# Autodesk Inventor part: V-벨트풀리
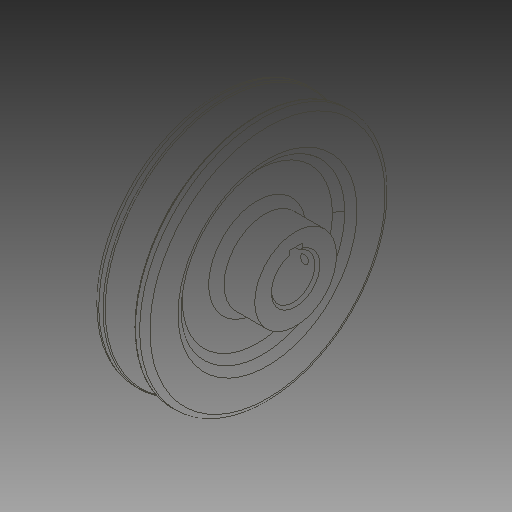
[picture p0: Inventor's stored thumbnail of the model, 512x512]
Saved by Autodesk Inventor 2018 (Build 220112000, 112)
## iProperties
Created: 2015-09
Part Number: V-벨트풀리
Material: 강철, 연강
Document SubType Name: Modeling
Designer: mduedu
Density: 7.86 g/cm^3
Mass: 779.014 g
Surface Area: 277.465 cm^2
Volume: 99.1112 cm^3
Appearance: 강철
Author: mduedu
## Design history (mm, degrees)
sketch "스케치1"
  geometry: L1 (-10, 0)-(10, 0); L2 (-10, 0)-(-10, 48); L3 (-10, 48)-(-5.976, 48); L4 (-5.976, 48)-(-2.154, 35.5); L5 (-2.154, 35.5)-(2.154, 35.5); L6 (2.154, 35.5)-(5.976, 48); L7 (5.976, 48)-(10, 48); L8 (10, 48)-(10, 0); L9 (0, 0)-(0, 35.5); L10 (-10, 43.5)-(10, 43.5); 3 further points
  constraints: 20 end point, 6 point on line, 3 perpendicular, 2 midpoint, 2 parallel, 2 symmetric about line, 1 coincident, 1 collinear, 1 equal length, 1 horizontal, 1 vertical, 1 vertical alignment
  dimensions: "d0" = 20 distance between parallel lines of L8 L2; "d2" = 96 diameter of L3 L1; "d3" = 87 diameter of L10 L1; "d4" = 4.5 distance between parallel lines of L10 L3 (derived); "d5" = 8 distance between parallel lines of L5 L10; "d6" = 9.2 distance of point (4.6, 43.5) point (-4.6, 43.5); "d7" = 34 deg angle of L6 L4
revolve "회전1" sketch "스케치1" stored, may be unused: angle "d8" = 90 deg
sketch "스케치2"
  geometry: C1 r 16 at (0, 0); 1 further point
  constraints: 1 centre point, 1 coincident
  dimensions: "d9" = 32 diameter of C1
extrude "돌출1" join sketch "스케치2" distance "d10" = 11; taper "d11" = 0 deg
fillet "모깎기1" dims "d12" = 1, "d13" = 0.5, "d14" = 2
sketch "스케치3"
  geometry: C1 r 16 at (0, 0) reference; C2 r 32 at (0, 0); 1 further point
  constraints: 1 centre point, 1 coincident
  dimensions: "d15" = 64 diameter of C2
extrude "돌출2" cut sketch "스케치3" distance "d16" = 4; taper "d17" = 0 deg
fillet "모깎기2" dims "d18" = 3
fillet "모깎기3" dims "d19" = 3
fillet "모깎기4" dims "d20" = 3
sketch "스케치4"
  geometry: C1 r 8.5 at (0, 0); 1 further point
  constraints: 1 centre point, 1 coincident
  dimensions: "d21" = 17 diameter of C1
extrude "돌출3" cut sketch "스케치4" extent not by distance; stored distance "d22" = 4; taper "d23" = 0 deg
sketch "스케치5"
  geometry: L1 (-2.5, 8.124)-(2.5, 8.124); L2 (2.5, 8.124)-(2.5, 10.8); L3 (2.5, 10.8)-(-2.5, 10.8); L4 (-2.5, 10.8)-(-2.5, 8.124); A1 r 8.5 centre (0, 0) between (-2.5, 8.124) and (2.5, 8.124) reference; 2 further points
  constraints: 8 end point, 3 point on circle, 2 parallel, 1 horizontal, 1 perpendicular, 1 vertical alignment
  dimensions: "d24" = 5 distance of L2.end L3.end; "d26" = 19.3 distance from line of L3 point (0, -8.5)
extrude "돌출4" cut sketch "스케치5" extent not by distance; stored distance "d27" = 4; taper "d28" = 0 deg
chamfer "모따기1" distance "d29" = 1; stored, may be unused: second distance "d30" = 2, angle "d31" = 45 deg
node "작업 평면1"
sketch "스케치6"
  geometry: L1 (-11, 16)-(-11, -16) reference; 2 further points
  constraints: 1 horizontal alignment
  dimensions: "d32" = 5 distance from line of point (-6, 0) L1
hole "구멍1" sketch "스케치6" at (-6, 0) diameter "d33" = 3.242; stored, may be unused: countersink angle "d37" = 90 deg, drill point angle "d39" = 118 deg; dims "d34" = 6, "d35" = 4, "d36" = 2, "d38" = 8
node "솔리드1"
mirror "대칭1"
